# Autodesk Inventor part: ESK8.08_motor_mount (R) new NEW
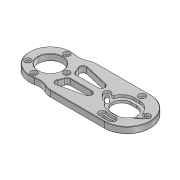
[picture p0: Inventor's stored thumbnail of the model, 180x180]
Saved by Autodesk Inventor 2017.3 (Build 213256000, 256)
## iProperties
Created: 2018-01
Part Number: ESK8.08_motor_mount (R) new NEW
Material: Aluminium 7075-T6
Document SubType Name: Modeling
Designer: Tobias
Density: 2.81 g/cm^3
Appearance: Machined - Aluminum
Mass: 107.599 g
Surface Area: 179.525 cm^2
Volume: 38.2913 cm^3
Author: Tobias
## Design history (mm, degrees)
sketch "Sketch1"
  geometry: L1 (0, 66.175)-(0, -66.175) reference; L2 (-56.3, 0)-(155.8, 0) reference; L3 (24, 29)-(96.5, 29); L4 (96.5, -29)-(24, -29); A1 r 26 centre (0, 0) between (5.824, 25.339) and (5.824, -25.339); A2 r 29 centre (96.5, 0) between (96.5, -29) and (96.5, 29); A3 r 22.5 centre (10.864, 47.268) between (5.824, 25.339) and (24, 29); A4 r 22.5 centre (10.864, -47.268) between (24, -29) and (5.824, -25.339); 1 further point
  constraints: 8 point on circle, 4 centre point, 4 end point, 2 symmetric about line, 2 tangent, 1 coincident, 1 horizontal, 1 parallel
  dimensions: "d144" = 52 diameter of A1; "d199" = 24 distance from line of L3.start L1; "d275" = 29 radius of A2 (derived); "d276" = 96.5 distance from line of L1 A2.centre; "d305" = 58 distance between parallel lines of L4 L3; "d526" = 22.5 radius of A3; "d527" = 45 diameter of A4 (derived)
extrude "Extrusion1" new body sketch "Sketch1" stored distance "d6" = 8; taper "d7" = 0 deg
sketch "Sketch3"
  geometry: L1 (0, 40.6)-(0, -40.6) reference; L2 (-56.3, 0)-(155.8, 0) reference; C1 r 15 at (0, 0); 1 further point
  constraints: 1 centre point, 1 coincident
  dimensions: "d12" = 30 diameter of C1
extrude "Extrusion3" cut sketch "Sketch3" distance "d13" = 89.75; taper "d14" = 0 deg
sketch "Sketch29"
  geometry: L1 (0, 40.6)-(0, -40.6) reference; L2 (-56.3, 0)-(155.8, 0) reference; L3 (96.5, 0)-(89.5, 0); L4 (96.5, 11.7)-(89.5, 11.7); L5 (89.5, -11.7)-(96.5, -11.7); A1 r 11.7 centre (96.5, 0) between (96.5, -11.7) and (96.5, 11.7); A2 r 11.7 centre (89.5, 0) between (89.5, 11.7) and (89.5, -11.7); 2 further points
  constraints: 8 end point, 4 point on circle, 4 tangent, 2 centre point, 2 point on line, 1 midpoint, 1 parallel
  dimensions: "d277" = 93 distance from line of L1 point (93, 0); "d278" = 7 distance of L3.end L3.start; "d279" = 23.4 distance between parallel lines of L4 L5
extrude "Extrusion23" cut sketch "Sketch29" distance "d280" = 69; taper "d281" = 0 deg
sketch "Sketch30"
  geometry: L1 (0, 85)-(0, -48) reference; L2 (-58.6, 0)-(169.6, 0) reference; L3 (93, 22)-(93, 0); L4 (93, 22)-(99.504, -21.517); L5 (86.496, -21.517)-(93, 22); L6 (118, 3.501)-(93, 22); L7 (111.499, -3)-(93, 22); L8 (93, 22)-(68, 3.501); L9 (74.501, -3)-(93, 22); C1 r 1.5 at (93, 22); A1 r 44 centre (93, 22) between (86.496, -21.517) and (99.504, -21.517); A2 r 31.1 centre (93, 22) between (118, 3.501) and (111.499, -3); A3 r 2.05 centre (99.504, -21.517) between (99.807, -23.544) and (99.201, -19.489); A4 r 2.05 centre (86.496, -21.517) between (86.799, -19.489) and (86.193, -23.544); A5 r 2.05 centre (118, 3.501) between (119.648, 2.282) and (116.352, 4.72); A6 r 2.05 centre (111.499, -3) between (110.28, -1.352) and (112.718, -4.648); A7 r 2.05 centre (74.501, -3) between (73.282, -4.648) and (75.72, -1.352); A8 r 2.05 centre (68, 3.501) between (69.648, 4.72) and (66.352, 2.282); A9 r 29.05 centre (93, 22) between (110.28, -1.352) and (116.352, 4.72); A10 r 33.15 centre (93, 22) between (66.352, 2.282) and (73.282, -4.648); A11 r 33.15 centre (93, 22) between (112.718, -4.648) and (119.648, 2.282); A12 r 41.95 centre (93, 22) between (86.799, -19.489) and (99.201, -19.489); A13 r 46.05 centre (93, 22) between (86.193, -23.544) and (99.807, -23.544); A14 r 29.05 centre (93, 22) between (69.648, 4.72) and (75.72, -1.352); 1 further point
  constraints: 30 point on circle, 15 centre point, 14 end point, 11 coincident, 9 tangent, 2 point on line, 1 concentric, 1 perpendicular, 2 other
  dimensions: "d282" = 93 distance between parallel lines of L1 L3 (derived); "d283" = 88 diameter of A1; "d284" = 62.2 diameter of A2; "d285" = 22 distance from line of L2 L3.start; "d288" = 17 deg angle of L5 L4 (derived); "d289" = 17 deg angle of L7 L6; "d290" = 17 deg angle of L8 L9 (derived); "d291" = 73 deg angle of L9 L7; "d292" = 2.05 radius of A4 (derived); "d293" = 2.05 radius of A8; "d294" = 3 diameter of C1
extrude "Extrusion24" cut sketch "Sketch30" distance "d286" = 69; taper "d287" = 0 deg
sketch "Sketch32"
  geometry: L1 (28.914, 8)-(56, 8); L2 (28.914, 4)-(56, 4); L3 (0, 40.6)-(0, -40.6) reference; L4 (-56.3, 0)-(155.8, 0) reference; L5 (26.889, 18.895)-(56.908, 11.895); A1 r 4 centre (28.914, 8) between (25.059, 6.933) and (28.914, 4); A2 r 4 centre (56, 8) between (56, 4) and (56.908, 11.895); A3 r 4 centre (25.981, 15) between (26.889, 18.895) and (22.517, 13); A4 r 26 centre (0, 0) between (25.059, 6.933) and (22.517, 13); 2 further points
  constraints: 8 end point, 8 point on circle, 6 tangent, 4 centre point, 1 coincident, 1 horizontal, 1 midpoint, 1 parallel
  dimensions: "d310" = 8 distance between parallel lines of L4 L1; "d430" = 4 radius of A2; "d431" = 4 radius of A3; "d435" = 26 radius of A4; "d437" = 15 distance from line of L4 A3.centre; "d453" = 56 distance from line of L1.end L3; "d460" = 13.1259 deg angle of L2 L5 (derived)
extrude "Extrusion26" cut sketch "Sketch32" distance "d307" = 10; taper "d308" = 0 deg
mirror "Mirror7"
sketch "Sketch63"
  geometry: C1 r 1.5 at (93, 22) reference; A1 r 2.05 centre (68, 3.501) between (69.648, 4.72) and (66.352, 2.282) reference; A2 r 2.05 centre (74.501, -3) between (73.282, -4.648) and (75.72, -1.352) reference; A3 r 33.15 centre (93, 22) between (66.352, 2.282) and (73.282, -4.648) reference; A4 r 29.05 centre (93, 22) between (69.648, 4.72) and (75.72, -1.352) reference; A5 r 29.05 centre (93, 22) between (110.28, -1.352) and (116.352, 4.72) reference; A6 r 2.05 centre (111.499, -3) between (110.28, -1.352) and (112.718, -4.648) reference; A7 r 33.15 centre (93, 22) between (112.718, -4.648) and (119.648, 2.282) reference; A8 r 2.05 centre (118, 3.501) between (119.648, 2.282) and (116.352, 4.72) reference; A9 r 41.95 centre (93, 22) between (86.799, -19.489) and (99.201, -19.489) reference; A10 r 2.05 centre (99.504, -21.517) between (99.807, -23.544) and (99.201, -19.489) reference; A11 r 46.05 centre (93, 22) between (86.193, -23.544) and (99.807, -23.544) reference; A12 r 2.05 centre (86.496, -21.517) between (86.799, -19.489) and (86.193, -23.544) reference; A13 r 4.2 centre (74.501, -3) between (72.003, -6.376) and (76.999, 0.376); A14 r 35.3 centre (93, 22) between (64.624, 1.003) and (72.003, -6.376); A15 r 4.2 centre (68, 3.501) between (71.376, 5.999) and (64.624, 1.003); A16 r 26.9 centre (93, 22) between (71.376, 5.999) and (76.999, 0.376); A17 r 27.1 centre (93, 22) between (109.12, 0.215) and (114.785, 5.88); A18 r 4 centre (111.499, -3) between (109.12, 0.215) and (113.878, -6.215); A19 r 35.1 centre (93, 22) between (113.878, -6.215) and (121.215, 1.122); A20 r 4 centre (118, 3.501) between (121.215, 1.122) and (114.785, 5.88); A21 r 39.8 centre (93, 22) between (87.117, -17.363) and (98.883, -17.363); A22 r 4.2 centre (86.496, -21.517) between (87.117, -17.363) and (85.876, -25.671); A23 r 48.2 centre (93, 22) between (85.876, -25.671) and (100.124, -25.671); A24 r 4.2 centre (99.504, -21.517) between (100.124, -25.671) and (98.883, -17.363); 1 further point
  constraints: 24 point on circle, 12 centre point, 9 other
  dimensions: "d456" = 4.2 radius of A15 (derived); "d458" = 4.2 radius of A22; "d459" = 4 radius of A20 (derived)
extrude "Extrusion54" cut sketch "Sketch63" distance "d454" = 3.3; taper "d455" = 0 deg
fillet "Fillet49" dims "d510" = 20
sketch "Sketch76"
  geometry: L1 (0, 40.6)-(0, -40.6) reference; L2 (-56.3, 0)-(155.8, 0) reference; L3 (89.5, 0)-(96.5, 0); L4 (89.5, -15.5)-(96.5, -15.5); L5 (96.5, 15.5)-(89.5, 15.5); A1 r 15.5 centre (89.5, 0) between (89.5, 15.5) and (89.5, -15.5); A2 r 15.5 centre (96.5, 0) between (96.5, -15.5) and (96.5, 15.5); 2 further points
  constraints: 8 end point, 4 point on circle, 4 tangent, 2 centre point, 2 point on line, 1 midpoint, 1 parallel
  dimensions: "d514" = 31 distance between parallel lines of L4 L5; "d515" = 93 distance from line of L1 point (93, 0) (derived); "d516" = 7 distance of L3.end L3.start
extrude "Extrusion66" cut sketch "Sketch76" distance "d517" = 3.3; taper "d518" = 0 deg
sketch "Sketch77"
  geometry: L1 (0, -40.6)-(0, 40.6) reference; L2 (-155.8, 0)-(56.3, 0) reference; L3 (-96.5, 0)-(-89.5, 0); L4 (-96.5, -27)-(-89.5, -27); L5 (-89.5, 27)-(-96.5, 27); A1 r 27 centre (-96.5, 0) between (-96.5, 27) and (-96.5, -27); A2 r 27 centre (-89.5, 0) between (-89.5, -27) and (-89.5, 27); 2 further points
  constraints: 8 end point, 4 point on circle, 4 tangent, 2 centre point, 2 point on line, 1 midpoint, 1 parallel
  dimensions: "d519" = 54 distance between parallel lines of L4 L5; "d520" = 7 distance of L3.end L3.start; "d521" = 93 distance from line of L1 point (-93, 0) (derived)
extrude "Extrusion67" cut sketch "Sketch77" distance "d522" = 1.5; taper "d523" = 0 deg
fillet "Fillet50" dims "d524" = 3
fillet "Fillet51" dims "d525" = 1.5
sketch "Sketch78"
  geometry: L1 (0, 40.6)-(0, -40.6) reference; L2 (-56.3, 0)-(155.8, 0) reference; L3 (0, -20.5)-(0, 0); L4 (-17.385, -10.863)-(0, 0); L5 (0, 20.5)-(0, 0); L6 (20.5, 0)-(0, 0); A1 r 20.5 centre (0, 0) between (-17.385, -10.863) and (0, 20.5); 1 further point
  constraints: 8 end point, 4 point on circle, 2 point on line, 1 centre point, 1 coincident, 1 midpoint
  dimensions: "d528" = 41 diameter of A1; "d529" = 90 deg angle of L1 L6; "d537" = 90 deg angle of L3 L2; "d538" = 90 deg angle of L2 L5 (derived); "d539" = 58 deg angle of L1 L4
hole "Hole6" sketch "Sketch78" at (-17.385, -10.863), (0, 20.5), (20.5, 0), (0, -20.5) diameter "d530" = 4.2; stored, may be unused: countersink angle "d534" = 90 deg, drill point angle "d536" = 118 deg; dims "d531" = 6, "d532" = 8, "d533" = 3, "d535" = 8
sketch "Sketch81"
  geometry: C1 r 1.5 at (93, 22) reference; 2 further points
  constraints: 1 coincident
hole "Hole8" sketch "Sketch81" at (93, 22) diameter "d559" = 3.9; stored, may be unused: countersink angle "d563" = 90 deg, drill point angle "d565" = 118 deg; dims "d560" = 6, "d561" = 8.4, "d562" = 3.3, "d564" = 8
chamfer "Chamfer18" distance "d511" = 0.5; stored, may be unused: second distance "d512" = 2, angle "d513" = 45 deg
body "Solid1"
other parameters: "d3" = 82, "d68" = 52, "d221" = 94, "d383" = 27, "d457" = 8, "sa_0" = 100000, "sa_1" = 92.4, "sa_2" = 0, "sa_3" = 0
